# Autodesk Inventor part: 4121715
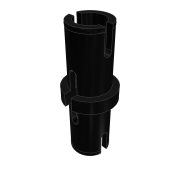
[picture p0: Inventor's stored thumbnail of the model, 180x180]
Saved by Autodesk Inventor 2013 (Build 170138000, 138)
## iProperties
Created: 2013-03
Part Number: 4121715
Material: Generic
Document SubType Name: Modeling
Designer: perblt
Density: 1 g/cm^3
Translation Standard: STEP AP203
FileName: 4121715
PreProcessor: PRO/ENGINEER BY PARAMETRIC TECHNOLOGY CORPORATION, 2010370
PostProcessor: Build: 138, Release: 2013 RTM - Date: Thu 03/01/2012
Sent Units: millimeter
Uncertainty: 0.001838370095962
Author: perblt
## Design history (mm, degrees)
node "41217151"
node "4121715"
node "Base1"
